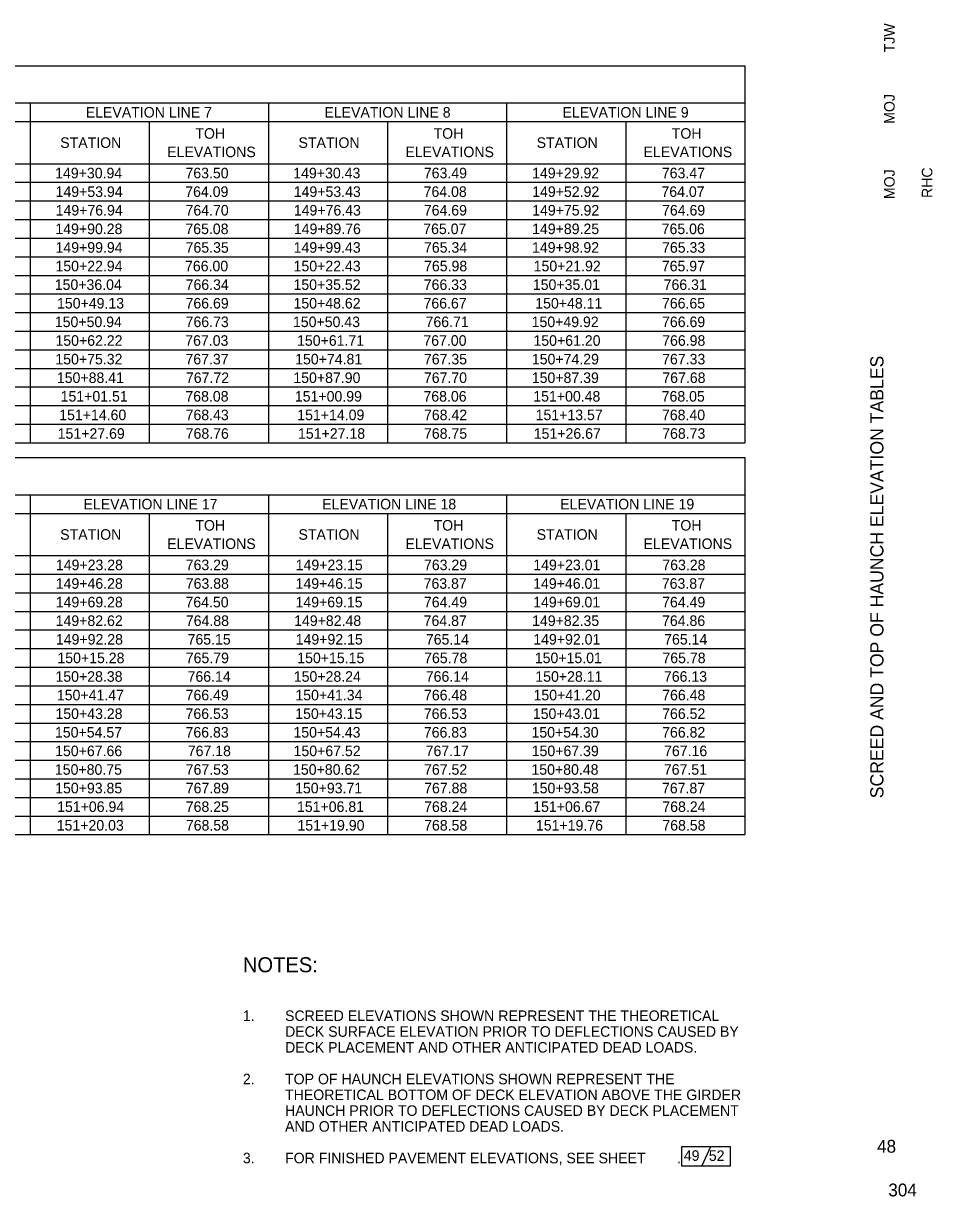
# Model space of a CAD drawing. Extents: x 2.7 to 33.4, y 0.7 to 21.3.
# Drawn here: x 21.34 to 33.41, y 1.08 to 16.66 of the extents above; entities that cross this region are included whole.
import ezdxf

# ---------------------------------------------------------------- set-up
doc = ezdxf.new("R2010")
doc.units = 0
doc.layers.add('BR_X_Beam_Object', color=7, linetype='Continuous')
doc.layers.add('BR_X_Slab_Object', color=7, linetype='Continuous')

msp = doc.modelspace()

# ---------------------------------------------------------------- linework, layer by layer
at = {"layer": 'BR_X_Beam_Object'}
msp.add_line((30.457, 1.742), (30.341, 1.492), dxfattribs=at)
msp.add_lwpolyline([(30.074, 1.492), (30.724, 1.492), (30.724, 1.742), (30.074, 1.742)], close=True, dxfattribs=at)
at = {"layer": 'BR_X_Slab_Object'}
for p, q in [((2.65, 16.1), (30.914, 16.1)), ((30.914, 16.1), (30.914, 11.093)), ((2.65, 15.606), (30.914, 15.606)), ((21.427, 15.606), (21.427, 11.093)), ((24.589, 15.606), (24.589, 11.093)), ((27.752, 15.606), (27.752, 11.093)), ((5.615, 15.359), (30.914, 15.359)), ((23.008, 15.359), (23.008, 11.093)), ((26.17, 15.359), (26.17, 11.093)), ((29.333, 15.359), (29.333, 11.093)), ((2.65, 14.799), (30.914, 14.799)), ((2.65, 14.552), (30.914, 14.552)), ((2.65, 14.304), (30.914, 14.304)), ((2.65, 14.057), (30.914, 14.057)), ((2.65, 13.81), (30.914, 13.81)), ((2.65, 13.563), (30.914, 13.563)), ((2.65, 13.316), (30.914, 13.316)), ((2.65, 13.069), (30.914, 13.069)), ((2.65, 12.822), (30.914, 12.822)), ((2.65, 12.575), (30.914, 12.575)), ((2.65, 12.328), (30.914, 12.328)), ((2.65, 12.081), (30.914, 12.081)), ((2.65, 11.834), (30.914, 11.834)), ((2.65, 11.587), (30.914, 11.587)), ((2.65, 11.34), (30.914, 11.34)), ((2.65, 11.093), (30.914, 11.093)), ((2.65, 10.896), (30.914, 10.896)), ((30.914, 10.896), (30.914, 5.889)), ((2.65, 10.402), (30.914, 10.402)), ((21.427, 10.402), (21.427, 5.889)), ((24.589, 10.402), (24.589, 5.889)), ((27.752, 10.402), (27.752, 5.889)), ((5.615, 10.155), (30.914, 10.155)), ((23.008, 10.155), (23.008, 5.889)), ((26.17, 10.155), (26.17, 5.889)), ((29.333, 10.155), (29.333, 5.889)), ((2.65, 9.595), (30.914, 9.595)), ((2.65, 9.348), (30.914, 9.348)), ((2.65, 9.101), (30.914, 9.101)), ((2.65, 8.854), (30.914, 8.854)), ((2.65, 8.607), (30.914, 8.607)), ((2.65, 8.36), (30.914, 8.36)), ((2.65, 8.113), (30.914, 8.113)), ((2.65, 7.866), (30.914, 7.866)), ((2.65, 7.618), (30.914, 7.618)), ((2.65, 7.371), (30.914, 7.371)), ((2.65, 7.124), (30.914, 7.124)), ((2.65, 6.877), (30.914, 6.877)), ((2.65, 6.63), (30.914, 6.63)), ((2.65, 6.383), (30.914, 6.383)), ((2.65, 6.136), (30.914, 6.136)), ((2.65, 5.889), (30.914, 5.889))]:
    msp.add_line(p, q, dxfattribs=at)

# ---------------------------------------------------------------- texts
at = {"layer": 'BR_X_Beam_Object'}
for s, height, p in [('ELEVATION LINE 7', 0.14, (22.165, 15.412)), ('ELEVATION LINE 8', 0.14, (25.333, 15.412)), ('ELEVATION LINE 9', 0.14, (28.493, 15.412)), ('TOH', 0.14, (23.62, 15.131)), ('TOH', 0.14, (26.782, 15.131)), ('TOH', 0.14, (29.944, 15.131)), ('STATION', 0.14, (21.826, 15.009)), ('STATION', 0.14, (24.989, 15.009)), ('STATION', 0.14, (28.151, 15.009)), ('ELEVATIONS', 0.14, (23.246, 14.886)), ('ELEVATIONS', 0.14, (26.408, 14.886)), ('ELEVATIONS', 0.14, (29.57, 14.886)), ('149+30.94', 0.14, (21.759, 14.605)), ('763.50', 0.14, (23.489, 14.605)), ('149+30.43', 0.14, (24.92, 14.605)), ('763.49', 0.14, (26.653, 14.605)), ('149+29.92', 0.14, (28.09, 14.605)), ('763.47', 0.14, (29.812, 14.605)), ('149+53.94', 0.14, (21.765, 14.358)), ('764.09', 0.14, (23.486, 14.358)), ('149+53.43', 0.14, (24.926, 14.358)), ('764.08', 0.14, (26.65, 14.358)), ('149+52.92', 0.14, (28.091, 14.358)), ('764.07', 0.14, (29.807, 14.358)), ('149+76.94', 0.14, (21.766, 14.111)), ('764.70', 0.14, (23.49, 14.111)), ('149+76.43', 0.14, (24.927, 14.111)), ('764.69', 0.14, (26.653, 14.111)), ('149+75.92', 0.14, (28.091, 14.111)), ('764.69', 0.14, (29.815, 14.111)), ('149+90.28', 0.14, (21.762, 13.864)), ('765.08', 0.14, (23.488, 13.864)), ('149+89.76', 0.14, (24.927, 13.864)), ('765.07', 0.14, (26.645, 13.864)), ('149+89.25', 0.14, (28.09, 13.864)), ('765.06', 0.14, (29.81, 13.864)), ('149+99.94', 0.14, (21.764, 13.617)), ('765.35', 0.14, (23.491, 13.617)), ('149+99.43', 0.14, (24.925, 13.617)), ('765.34', 0.14, (26.655, 13.617)), ('149+98.92', 0.14, (28.089, 13.617)), ('765.33', 0.14, (29.815, 13.617)), ('150+22.94', 0.14, (21.763, 13.37)), ('766.00', 0.14, (23.483, 13.37)), ('150+22.43', 0.14, (24.924, 13.37)), ('765.98', 0.14, (26.656, 13.37)), ('150+21.92', 0.14, (28.111, 13.37)), ('765.97', 0.14, (29.812, 13.37)), ('150+36.04', 0.14, (21.754, 13.123)), ('766.34', 0.14, (23.491, 13.123)), ('150+35.52', 0.14, (24.923, 13.123)), ('766.33', 0.14, (26.652, 13.123)), ('150+35.01', 0.14, (28.1, 13.123)), ('766.31', 0.14, (29.836, 13.123)), ('150+49.13', 0.14, (21.784, 12.876)), ('766.69', 0.14, (23.49, 12.876)), ('150+48.62', 0.14, (24.923, 12.876)), ('766.67', 0.14, (26.649, 12.876)), ('150+48.11', 0.14, (28.132, 12.876)), ('766.65', 0.14, (29.814, 12.876)), ('150+50.94', 0.14, (21.755, 12.629)), ('766.73', 0.14, (23.491, 12.629)), ('150+50.43', 0.14, (24.916, 12.629)), ('766.71', 0.14, (26.676, 12.629)), ('150+49.92', 0.14, (28.084, 12.629)), ('766.69', 0.14, (29.815, 12.629)), ('150+62.22', 0.14, (21.763, 12.381)), ('767.03', 0.14, (23.486, 12.381)), ('150+61.71', 0.14, (24.97, 12.381)), ('767.00', 0.14, (26.647, 12.381)), ('150+61.20', 0.14, (28.108, 12.381)), ('766.98', 0.14, (29.817, 12.381)), ('150+75.32', 0.14, (21.762, 12.134)), ('767.37', 0.14, (23.489, 12.134)), ('150+74.81', 0.14, (24.945, 12.134)), ('767.35', 0.14, (26.654, 12.134)), ('150+74.29', 0.14, (28.087, 12.134)), ('767.33', 0.14, (29.816, 12.134)), ('150+88.41', 0.14, (21.782, 11.887)), ('767.72', 0.14, (23.495, 11.887)), ('150+87.90', 0.14, (24.921, 11.887)), ('767.70', 0.14, (26.654, 11.887)), ('150+87.39', 0.14, (28.086, 11.887)), ('767.68', 0.14, (29.819, 11.887)), ('151+01.51', 0.14, (21.832, 11.64)), ('768.08', 0.14, (23.488, 11.64)), ('151+00.99', 0.14, (24.941, 11.64)), ('768.06', 0.14, (26.648, 11.64)), ('151+00.48', 0.14, (28.106, 11.64)), ('768.05', 0.14, (29.81, 11.64)), ('151+14.60', 0.14, (21.813, 11.393)), ('768.43', 0.14, (23.491, 11.393)), ('151+14.09', 0.14, (24.973, 11.393)), ('768.42', 0.14, (26.655, 11.393)), ('151+13.57', 0.14, (28.137, 11.393)), ('768.40', 0.14, (29.814, 11.393)), ('151+27.69', 0.14, (21.793, 11.146)), ('768.76', 0.14, (23.492, 11.146)), ('151+27.18', 0.14, (24.983, 11.146)), ('768.75', 0.14, (26.655, 11.146)), ('151+26.67', 0.14, (28.112, 11.146)), ('768.73', 0.14, (29.817, 11.146)), ('ELEVATION LINE 17', 0.14, (22.135, 10.208)), ('ELEVATION LINE 18', 0.14, (25.303, 10.208)), ('ELEVATION LINE 19', 0.14, (28.463, 10.208)), ('TOH', 0.14, (23.62, 9.927)), ('TOH', 0.14, (26.782, 9.927)), ('TOH', 0.14, (29.944, 9.927)), ('STATION', 0.14, (21.826, 9.805)), ('ELEVATIONS', 0.14, (23.246, 9.682)), ('STATION', 0.14, (24.989, 9.805)), ('ELEVATIONS', 0.14, (26.408, 9.682)), ('STATION', 0.14, (28.151, 9.805)), ('ELEVATIONS', 0.14, (29.57, 9.682)), ('149+23.28', 0.14, (21.769, 9.401)), ('763.29', 0.14, (23.492, 9.401)), ('149+23.15', 0.14, (24.952, 9.401)), ('763.29', 0.14, (26.655, 9.401)), ('149+23.01', 0.14, (28.106, 9.401)), ('763.28', 0.14, (29.819, 9.401)), ('149+46.28', 0.14, (21.767, 9.154)), ('763.88', 0.14, (23.493, 9.154)), ('149+46.15', 0.14, (24.951, 9.154)), ('763.87', 0.14, (26.65, 9.154)), ('149+46.01', 0.14, (28.104, 9.154)), ('763.87', 0.14, (29.812, 9.154)), ('149+69.28', 0.14, (21.767, 8.907)), ('764.50', 0.14, (23.489, 8.907)), ('149+69.15', 0.14, (24.95, 8.907)), ('764.49', 0.14, (26.654, 8.907)), ('149+69.01', 0.14, (28.104, 8.907)), ('764.49', 0.14, (29.816, 8.907)), ('149+82.62', 0.14, (21.766, 8.66)), ('764.88', 0.14, (23.494, 8.66)), ('149+82.48', 0.14, (24.931, 8.66)), ('764.87', 0.14, (26.651, 8.66)), ('149+82.35', 0.14, (28.09, 8.66)), ('764.86', 0.14, (29.815, 8.66)), ('149+92.28', 0.14, (21.769, 8.413)), ('765.15', 0.14, (23.517, 8.413)), ('149+92.15', 0.14, (24.952, 8.413)), ('765.14', 0.14, (26.68, 8.413)), ('149+92.01', 0.14, (28.106, 8.413)), ('765.14', 0.14, (29.843, 8.413)), ('150+15.28', 0.14, (21.789, 8.166)), ('765.79', 0.14, (23.493, 8.166)), ('150+15.15', 0.14, (24.973, 8.166)), ('765.78', 0.14, (26.657, 8.166)), ('150+15.01', 0.14, (28.126, 8.166)), ('765.78', 0.14, (29.82, 8.166)), ('150+28.38', 0.14, (21.763, 7.919)), ('766.14', 0.14, (23.517, 7.919)), ('150+28.24', 0.14, (24.927, 7.919)), ('766.14', 0.14, (26.679, 7.919)), ('150+28.11', 0.14, (28.133, 7.919)), ('766.13', 0.14, (29.84, 7.919)), ('150+41.47', 0.14, (21.782, 7.672)), ('766.49', 0.14, (23.491, 7.672)), ('150+41.34', 0.14, (24.948, 7.672)), ('766.48', 0.14, (26.655, 7.672)), ('150+41.20', 0.14, (28.109, 7.672)), ('766.48', 0.14, (29.817, 7.672)), ('150+43.28', 0.14, (21.763, 7.425)), ('766.53', 0.14, (23.49, 7.425)), ('150+43.15', 0.14, (24.946, 7.425)), ('766.53', 0.14, (26.653, 7.425)), ('150+43.01', 0.14, (28.1, 7.425)), ('766.52', 0.14, (29.816, 7.425)), ('150+54.57', 0.14, (21.757, 7.178)), ('766.83', 0.14, (23.49, 7.178)), ('150+54.43', 0.14, (24.922, 7.178)), ('766.83', 0.14, (26.653, 7.178)), ('150+54.30', 0.14, (28.082, 7.178)), ('766.82', 0.14, (29.816, 7.178)), ('150+67.66', 0.14, (21.759, 6.931)), ('767.18', 0.14, (23.52, 6.931)), ('150+67.52', 0.14, (24.924, 6.931)), ('767.17', 0.14, (26.677, 6.931)), ('150+67.39', 0.14, (28.085, 6.931)), ('767.16', 0.14, (29.842, 6.931)), ('150+80.75', 0.14, (21.756, 6.684)), ('767.53', 0.14, (23.492, 6.684)), ('150+80.62', 0.14, (24.917, 6.684)), ('767.52', 0.14, (26.656, 6.684)), ('150+80.48', 0.14, (28.081, 6.684)), ('767.51', 0.14, (29.839, 6.684)), ('150+93.85', 0.14, (21.759, 6.437)), ('767.89', 0.14, (23.493, 6.437)), ('150+93.71', 0.14, (24.944, 6.437)), ('767.88', 0.14, (26.657, 6.437)), ('150+93.58', 0.14, (28.086, 6.437)), ('767.87', 0.14, (29.814, 6.437)), ('151+06.94', 0.14, (21.785, 6.19)), ('768.25', 0.14, (23.493, 6.19)), ('151+06.81', 0.14, (24.969, 6.19)), ('768.24', 0.14, (26.657, 6.19)), ('151+06.67', 0.14, (28.105, 6.19)), ('768.24', 0.14, (29.819, 6.19)), ('151+20.03', 0.14, (21.78, 5.943)), ('768.58', 0.14, (23.494, 5.943)), ('151+19.90', 0.14, (24.975, 5.943)), ('768.58', 0.14, (26.657, 5.943)), ('151+19.76', 0.14, (28.141, 5.943)), ('768.58', 0.14, (29.819, 5.943)), ('NOTES:', 0.2, (24.251, 4.061)), ('1.', 0.14, (24.251, 3.414)), ('SCREED ELEVATIONS SHOWN REPRESENT THE THEORETICAL ', 0.14, (24.811, 3.414)), ('DECK SURFACE ELEVATION PRIOR TO DEFLECTIONS CAUSED BY ', 0.14, (24.811, 3.204)), ('DECK PLACEMENT AND OTHER ANTICIPATED DEAD LOADS.', 0.14, (24.811, 2.994)), ('2.', 0.14, (24.251, 2.574)), ('TOP OF HAUNCH ELEVATIONS SHOWN REPRESENT THE ', 0.14, (24.811, 2.574)), ('THEORETICAL BOTTOM OF DECK ELEVATION ABOVE THE GIRDER ', 0.14, (24.811, 2.364)), ('HAUNCH PRIOR TO DEFLECTIONS CAUSED BY DECK PLACEMENT ', 0.14, (24.811, 2.154)), ('AND OTHER ANTICIPATED DEAD LOADS.', 0.14, (24.811, 1.944)), ('48', 0.17, (32.669, 1.665)), ('3.', 0.14, (24.251, 1.524)), ('FOR FINISHED PAVEMENT ELEVATIONS, SEE SHEET        .', 0.14, (24.811, 1.524)), ('49', 0.14, (30.104, 1.557)), ('52', 0.14, (30.436, 1.556)), ('304', 0.17, (32.818, 1.085))]:
    msp.add_text(s, height=height, dxfattribs=at).set_placement(p)
at = {"layer": 'BR_X_Slab_Object'}
for s, height, p in [('TJW', 0.14, (32.903, 16.278)), ('MOJ', 0.14, (32.903, 15.329)), ('MOJ', 0.14, (32.903, 14.329)), ('RHC', 0.14, (33.403, 14.344)), ('SCREED AND TOP OF HAUNCH ELEVATION TABLES', 0.175, (32.754, 6.372))]:
    msp.add_text(s, height=height, rotation=90, dxfattribs=at).set_placement(p)

doc.saveas('drawing.dxf')
